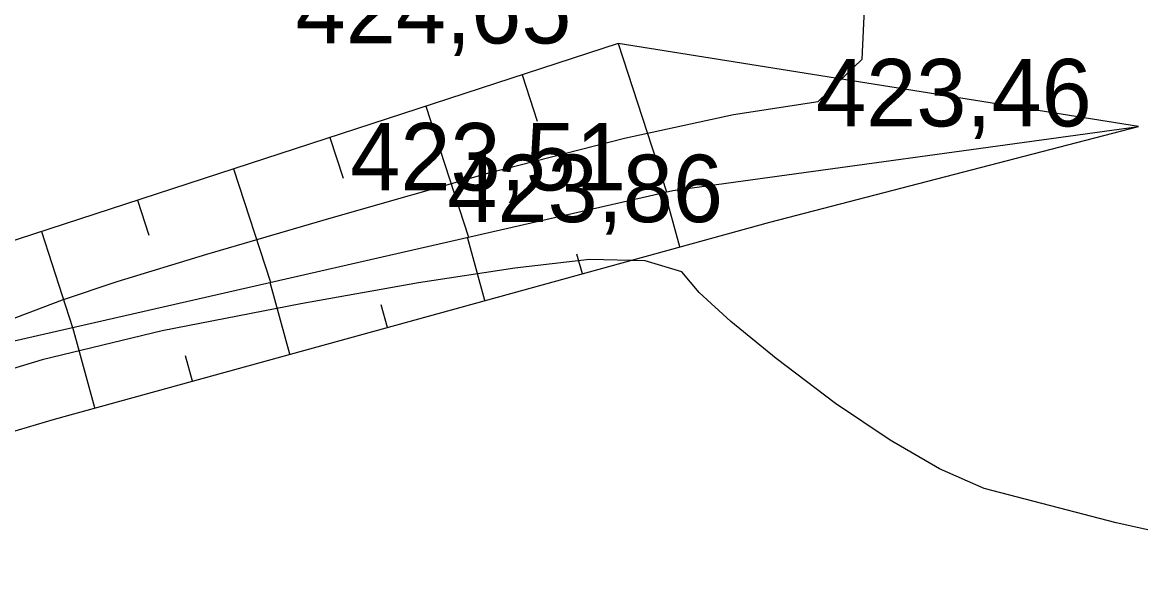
# Model space of a CAD drawing. Extents: x -574342 to -507939, y -1144044 to -1123894.
# Drawn here: x -508541.26 to -508524.67, y -1143747.63 to -1143739.49 of the extents above; entities that cross this region are included whole.
import ezdxf

# ---------------------------------------------------------------- set-up
doc = ezdxf.new("R2010")
doc.units = 0
for name, color, linetype in [('60', 7, 'Continuous'), ('61', 7, 'Continuous'), ('Level 255', 7, 'Continuous'), ('VRST VEDL', 7, 'Continuous')]:
    doc.layers.add(name, color=color, linetype=linetype)

msp = doc.modelspace()

# ---------------------------------------------------------------- linework, layer by layer
at = {"layer": '60'}
msp.add_lwpolyline([(-508547.06, -1143747.23), (-508540.78, -1143745.37), (-508530.17, -1143742.45), (-508524.7, -1143741.03), (-508532.42, -1143739.8), (-508541.78, -1143742.85), (-508547.24, -1143744.9)], close=True, dxfattribs=at)
msp.add_lwpolyline([(-508547.06, -1143747.23), (-508540.78, -1143745.37), (-508530.17, -1143742.45), (-508524.7, -1143741.03), (-508532.42, -1143739.8), (-508541.78, -1143742.85), (-508547.24, -1143744.9)], close=True, dxfattribs=at)
msp.add_lwpolyline([(-508545.73, -1143746.01), (-508541.38, -1143744.21), (-508531.61, -1143741.98), (-508524.7, -1143741.03)], dxfattribs=at)
msp.add_lwpolyline([(-508545.73, -1143746.01), (-508541.38, -1143744.21), (-508531.61, -1143741.98), (-508524.7, -1143741.03)], dxfattribs=at)
at = {"layer": '61'}
for p, q in [((-508532.42, -1143739.8), (-508531.703, -1143742.001)), ((-508532.42, -1143739.8), (-508531.703, -1143742.001)), ((-508533.846, -1143740.265), (-508533.621, -1143740.955)), ((-508533.846, -1143740.265), (-508533.621, -1143740.955)), ((-508535.272, -1143740.729), (-508534.64, -1143742.671)), ((-508535.272, -1143740.729), (-508534.64, -1143742.671)), ((-508536.699, -1143741.194), (-508536.502, -1143741.798)), ((-508536.699, -1143741.194), (-508536.502, -1143741.798)), ((-508538.125, -1143741.659), (-508537.576, -1143743.342)), ((-508538.125, -1143741.659), (-508537.576, -1143743.342)), ((-508539.551, -1143742.124), (-508539.382, -1143742.641)), ((-508539.551, -1143742.124), (-508539.382, -1143742.641)), ((-508531.505, -1143742.817), (-508531.728, -1143742.007)), ((-508531.505, -1143742.817), (-508531.728, -1143742.007)), ((-508540.977, -1143742.588), (-508540.513, -1143744.012)), ((-508540.977, -1143742.588), (-508540.513, -1143744.012)), ((-508534.397, -1143743.613), (-508534.656, -1143742.675)), ((-508534.397, -1143743.613), (-508534.656, -1143742.675)), ((-508532.951, -1143743.215), (-508533.031, -1143742.924)), ((-508532.951, -1143743.215), (-508533.031, -1143742.924)), ((-508537.29, -1143744.409), (-508537.583, -1143743.343)), ((-508537.29, -1143744.409), (-508537.583, -1143743.343)), ((-508535.844, -1143744.011), (-508535.935, -1143743.678)), ((-508535.844, -1143744.011), (-508535.935, -1143743.678)), ((-508540.182, -1143745.206), (-508540.511, -1143744.012)), ((-508540.182, -1143745.206), (-508540.511, -1143744.012)), ((-508538.736, -1143744.807), (-508538.84, -1143744.431)), ((-508538.736, -1143744.807), (-508538.84, -1143744.431))]:
    msp.add_line(p, q, dxfattribs=at)
at = {"layer": 'VRST VEDL'}
for points in [[(-508541.594, -1143743.955), (-508540.665, -1143743.604), (-508539.851, -1143743.331), (-508538.523, -1143742.925), (-508536.678, -1143742.386), (-508534.318, -1143741.714), (-508532.328, -1143741.203), (-508530.707, -1143740.853), (-508529.455, -1143740.662), (-508528.802, -1143740.034), (-508528.749, -1143738.968)], [(-508521.777, -1143747.633), (-508525.033, -1143746.912), (-508526.991, -1143746.403), (-508527.651, -1143746.107), (-508528.386, -1143745.686), (-508529.194, -1143745.141), (-508530.076, -1143744.471), (-508530.751, -1143743.922), (-508531.217, -1143743.494), (-508531.475, -1143743.187), (-508532.018, -1143743.025), (-508532.845, -1143743.006), (-508533.955, -1143743.132), (-508535.383, -1143743.35), (-508537.127, -1143743.661), (-508539.187, -1143744.064), (-508540.963, -1143744.491), (-508542.455, -1143744.944)]]:
    msp.add_lwpolyline(points, dxfattribs=at)

# ---------------------------------------------------------------- texts
at = {"layer": 'Level 255'}
for s, p in [('424,65', (-508537.205, -1143739.8)), ('423,46', (-508529.485, -1143741.03)), ('423,51', (-508536.395, -1143741.98)), ('423,86', (-508534.955, -1143742.45))]:
    msp.add_text(s, height=1, dxfattribs=at).set_placement(p)

doc.saveas('drawing.dxf')
